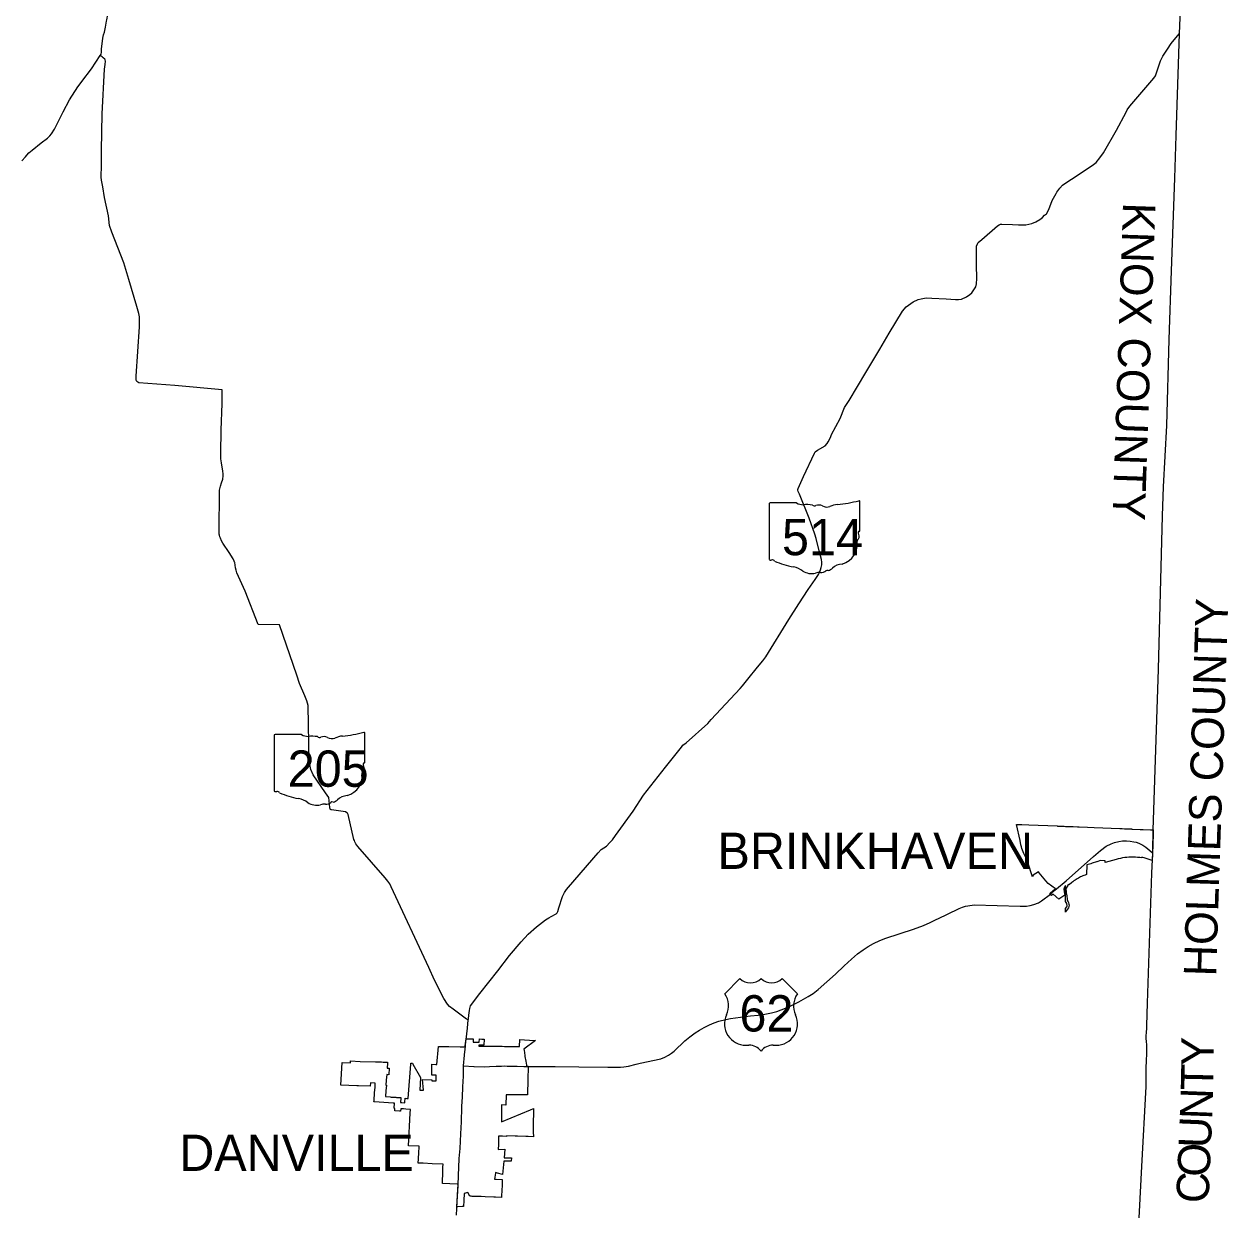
# Model space of a CAD drawing. Extents: x 1851937 to 2123937, y 789467 to 965467.
# Drawn here: x 2021685 to 2058846, y 888471 to 925060 of the extents above; entities that cross this region are included whole.
import ezdxf

# ---------------------------------------------------------------- set-up
doc = ezdxf.new("R2010")
doc.units = 0
for name, color, linetype in [('GM_X_Corporation', 7, 'Continuous'), ('GM_X_Corporation_Text', 7, 'Continuous'), ('GM_X_County', 7, 'Continuous'), ('GM_X_County_Text', 7, 'Continuous'), ('GM_X_State_Location', 7, 'Continuous'), ('GM_X_State_Route', 7, 'Continuous'), ('GM_X_State_Shield', 7, 'Continuous'), ('GM_X_US_Location', 7, 'Continuous'), ('GM_X_US_Route', 7, 'Continuous'), ('GM_X_US_Shield', 7, 'Continuous')]:
    doc.layers.add(name, color=color, linetype=linetype)

msp = doc.modelspace()

# ---------------------------------------------------------------- linework, layer by layer
at = {"layer": 'GM_X_Corporation'}
for points in [[(2052321, 900367), (2052352, 900365), (2052484, 900360), (2052703, 900351), (2053571, 900317), (2053588, 900316), (2053716, 900311), (2053718, 900311), (2053746, 900310), (2053776, 900308), (2053784, 900308), (2053794, 900308), (2053833, 900306), (2053913, 900303), (2053916, 900303), (2053922, 900303), (2053979, 900300), (2053982, 900300), (2053985, 900300), (2054057, 900297), (2054065, 900297), (2054208, 900291), (2054246, 900290), (2054254, 900289), (2054513, 900279), (2054719, 900271), (2055512, 900239), (2055579, 900236), (2055655, 900233), (2055792, 900228), (2055867, 900225), (2055883, 900224), (2055889, 900224), (2055898, 900224), (2056133, 900214), (2056231, 900210), (2056453, 900201), (2056542, 900198), (2056537, 900024), (2056536, 899999), (2056535, 899974), (2056531, 899854), (2056529, 899775), (2056527, 899731), (2056526, 899688), (2056521, 899532), (2056520, 899491), (2056518, 899449), (2056512, 899250), (2056449, 899275), (2056386, 899297), (2056322, 899318), (2056257, 899336), (2056192, 899352), (2056190, 899336), (2056124, 899344), (2056057, 899350), (2055991, 899354), (2055925, 899356), (2055858, 899355), (2055792, 899352), (2055725, 899347), (2055659, 899340), (2055593, 899330), (2055528, 899318), (2055463, 899304), (2055399, 899288), (2055056, 899194), (2055058, 899244), (2054915, 899249), (2054801, 899213), (2054787, 899208), (2054658, 899167), (2054613, 899153), (2054489, 899114), (2054480, 898818), (2054441, 898805), (2054403, 898791), (2054365, 898776), (2054328, 898759), (2054297, 898745), (2054267, 898729), (2054231, 898710), (2054195, 898689), (2054161, 898667), (2054127, 898644), (2054094, 898620), (2054061, 898595), (2054030, 898569), (2053948, 898500), (2053919, 898508), (2053907, 898478), (2053885, 898446), (2053856, 898402), (2053846, 898378), (2053843, 898356), (2053850, 898306), (2053858, 898247), (2053863, 898210), (2053870, 898159), (2053887, 898057), (2053887, 898049), (2053887, 898025), (2053891, 898012), (2053910, 897980), (2053920, 897957), (2053925, 897947), (2053936, 897910), (2053944, 897874), (2053940, 897830), (2053923, 897797), (2053836, 897665), (2053834, 897663), (2053834, 897665), (2053834, 897772), (2053871, 897827), (2053881, 897847), (2053883, 897871), (2053878, 897895), (2053869, 897923), (2053869, 897926), (2053857, 897952), (2053836, 897987), (2053834, 897993), (2053833, 898476), (2053803, 898430), (2053787, 898394), (2053785, 898375), (2053783, 898355), (2053790, 898298), (2053802, 898214), (2053807, 898174), (2053784, 898159), (2053630, 898057), (2053447, 898211), (2053404, 898175), (2053393, 898187), (2053354, 898232), (2053465, 898334), (2053519, 898381), (2053293, 898546), (2053228, 898622), (2053016, 898874), (2052995, 898899), (2052831, 898805), (2052815, 898748), (2052668, 899194), (2052651, 899230), (2052606, 899344), (2052547, 899468), (2052488, 899624), (2052470, 899674), (2052452, 899732), (2052431, 899865)], [(2032719, 893036), (2032769, 893034), (2032904, 893030), (2032902, 893000), (2032890, 892847), (2032956, 892844), (2032943, 892644), (2032878, 892647), (2032865, 892475), (2032855, 892325), (2032870, 892324), (2032857, 892145), (2032845, 891966), (2032987, 891957), (2033021, 891954), (2033163, 891945), (2033178, 891944), (2033318, 891935), (2033317, 891922), (2033308, 891786), (2033341, 891784), (2033441, 891778), (2033442, 891797), (2033447, 891917), (2033502, 891913), (2033542, 891911), (2033622, 892971), (2033624, 893001), (2033671, 892998), (2033688, 892967), (2033922, 892555), (2033902, 892168), (2034015, 892161), (2033987, 892497), (2034269, 892480), (2034268, 892459), (2034402, 892451), (2034408, 892586), (2034409, 892625), (2034275, 892630), (2034274, 892778), (2034273, 892936), (2034273, 892966), (2034397, 892959), (2034424, 892958), (2034480, 893517), (2034608, 893514), (2034801, 893509), (2035142, 893501), (2035273, 893498), (2035303, 893496), (2035305, 893514), (2035316, 893630), (2035318, 893655), (2035320, 893680), (2035327, 893754), (2035357, 893754), (2035466, 893752), (2035550, 893750), (2035546, 893649), (2035735, 893644), (2035739, 893746), (2035815, 893744), (2035886, 893743), (2035882, 893550), (2035808, 893551), (2035728, 893552), (2035726, 893528), (2035749, 893527), (2035807, 893527), (2035881, 893526), (2035986, 893525), (2036089, 893523), (2036228, 893522), (2036358, 893520), (2036362, 893520), (2036405, 893520), (2036446, 893519), (2036512, 893518), (2036578, 893518), (2036644, 893517), (2036710, 893516), (2036776, 893515), (2036792, 893515), (2036842, 893515), (2036849, 893514), (2036908, 893514), (2036974, 893513), (2036986, 893727), (2037426, 893698), (2037473, 893695), (2037114, 893431), (2037120, 893397), (2037144, 893235), (2037148, 893211), (2037148, 893207), (2037171, 893056), (2037190, 892934), (2037195, 892904), (2037246, 892904), (2037245, 892874), (2037236, 892509), (2037223, 892019), (2036593, 892025), (2036568, 892026), (2036555, 891698), (2036426, 891713), (2036418, 891193), (2037314, 891562), (2037408, 891601), (2037407, 891496), (2037406, 891434), (2037404, 891204), (2037402, 891068), (2037402, 890979), (2037401, 890944), (2037401, 890913), (2037403, 890884), (2037412, 890731), (2037245, 890736), (2037171, 890738), (2036917, 890746), (2036847, 890748), (2036581, 890760), (2036580, 890741), (2036573, 890741), (2036457, 890745), (2036396, 890747), (2036335, 890750), (2036331, 890645), (2036331, 890624), (2036330, 890603), (2036329, 890584), (2036329, 890569), (2036325, 890479), (2036325, 890463), (2036321, 890368), (2036320, 890338), (2036528, 890343), (2036504, 890073), (2036733, 890077), (2036724, 889977), (2036495, 889974), (2036458, 889565), (2036298, 889601), (2036242, 889625), (2036240, 889615), (2036239, 889607), (2036209, 889420), (2036254, 889418), (2036448, 889411), (2036442, 889276), (2036439, 889186), (2036436, 889126), (2036425, 888859), (2036239, 888865), (2036186, 888867), (2035915, 888876), (2035794, 888881), (2035713, 888883), (2035632, 888886), (2035521, 888890), (2035483, 888892), (2035448, 888893), (2035387, 889008), (2035269, 888982), (2035256, 888762), (2035245, 888577), (2035213, 888575), (2035076, 888569), (2035046, 888567), (2035056, 888752), (2035065, 888919), (2035066, 888938), (2035084, 889261), (2035058, 889262), (2035054, 889262), (2034599, 889287), (2034603, 889402), (2034608, 889557), (2034610, 889617), (2034612, 889692), (2034615, 889794), (2034618, 889883), (2034287, 889897), (2034004, 889909), (2033853, 889915), (2033854, 889932), (2033859, 890025), (2033860, 890044), (2033861, 890072), (2033865, 890143), (2033866, 890160), (2033867, 890176), (2033870, 890230), (2033880, 890413), (2033881, 890433), (2033560, 890447), (2033547, 890448), (2033602, 891460), (2033609, 891574), (2033470, 891583), (2033401, 891587), (2033391, 891588), (2033323, 891592), (2033312, 891593), (2033308, 891518), (2033272, 891520), (2033131, 891529), (2033134, 891604), (2033111, 891606), (2033113, 891642), (2033117, 891737), (2033119, 891767), (2033083, 891769), (2032499, 891806), (2032485, 891807), (2032487, 891837), (2032495, 891943), (2032498, 891987), (2032505, 892089), (2032511, 892166), (2032518, 892255), (2032524, 892344), (2032527, 892381), (2032376, 892389), (2032370, 892289), (2032007, 892301), (2031958, 892303), (2031464, 892319), (2031505, 893021), (2031760, 893013), (2031761, 893040), (2031763, 893070), (2032064, 893055), (2032532, 893041), (2032574, 893040), (2032640, 893038)]]:
    msp.add_lwpolyline(points, close=True, dxfattribs=at)
at = {"layer": 'GM_X_County'}
msp.add_lwpolyline([(2057387, 925735), (2057341, 924765), (2057236, 921624), (2057193, 920311), (2057098, 917443), (2057025, 915328), (2056946, 912676), (2056845, 910778), (2056821, 909883), (2056692, 905152), (2056529, 900191), (2056527, 900003), (2056520, 899740), (2056513, 899490), (2056492, 898858), (2056354, 894848), (2056334, 894166), (2056331, 894092), (2056325, 893939), (2056317, 893849), (2056312, 893777), (2056311, 893750), (2056318, 893677), (2056334, 893555), (2056336, 893469), (2056330, 893288), (2056319, 893081), (2056309, 892841), (2056314, 892278), (2056177, 889807), (2056002, 886440)], dxfattribs=at)
at = {"layer": 'GM_X_State_Route'}
for p, q in [((2029574, 906524), (2028910, 906536)), ((2035251, 892913), (2035278, 893241))]:
    msp.add_line(p, q, dxfattribs=at)
for points in [[(2024079, 924295), (2024091, 924454), (2024120, 924627), (2024142, 924729), (2024166, 924813), (2024178, 924861), (2024195, 924962), (2024225, 925154), (2024237, 925195), (2024266, 925358)], [(2053553, 919853), (2053564, 919874), (2053655, 919999), (2053741, 920091), (2053900, 920203), (2054126, 920351), (2054699, 920729), (2054777, 920789), (2054889, 920929), (2055003, 921089), (2055408, 921787), (2055703, 922344), (2055738, 922412), (2055816, 922525), (2056564, 923387), (2056606, 923460), (2056643, 923558), (2056731, 923835), (2056763, 923923), (2056834, 924072), (2056976, 924291), (2057097, 924461), (2057342, 924763)], [(2023418, 923218), (2023467, 923286), (2023766, 923681), (2023902, 923882), (2024034, 924087), (2024060, 924131), (2024071, 924196), (2024079, 924295)], [(2028910, 906536), (2028512, 907560), (2028248, 908130), (2028231, 908208), (2028214, 908286), (2028189, 908444), (2028185, 908462), (2028174, 908489), (2028140, 908564), (2028021, 908756), (2027822, 909043), (2027784, 909112), (2027745, 909197), (2027730, 909237), (2027716, 909287), (2027710, 909324), (2027706, 909359), (2027716, 910683), (2027747, 910800), (2027780, 910910), (2027816, 911014), (2027835, 911123), (2027829, 911187), (2027821, 911261), (2027783, 911525), (2027761, 911642), (2027758, 911816), (2027774, 912532), (2027798, 913358), (2027800, 913773), (2026334, 913904), (2025223, 913996), (2025197, 914012), (2025171, 914035), (2025159, 914050), (2025148, 914071), (2025144, 914093), (2025142, 914197), (2025247, 915720), (2025252, 915970), (2025249, 916031), (2025243, 916076), (2025232, 916134), (2025170, 916343), (2024920, 917178), (2024760, 917692), (2024397, 918645), (2024321, 918841), (2024296, 919139), (2024168, 919710), (2024114, 920041), (2024072, 920249), (2024065, 920338), (2024070, 920459), (2024072, 920586), (2024072, 921156), (2024093, 922294), (2024166, 923668), (2024188, 923818), (2024194, 923919), (2024189, 923955), (2024182, 923982), (2024130, 924023), (2024096, 924049), (2024034, 924087)], [(2021619, 920841), (2021725, 920964), (2021772, 921018), (2021836, 921085), (2021940, 921174), (2022214, 921395), (2022408, 921542), (2022484, 921610), (2022532, 921679), (2022622, 921819), (2022695, 921958), (2022897, 922355), (2023088, 922719), (2023347, 923120), (2023418, 923218)], [(2052386, 918870), (2052501, 918870), (2052612, 918867), (2052697, 918886), (2052790, 918910), (2052921, 918961), (2053042, 919035), (2053121, 919095), (2053188, 919163), (2053241, 919208), (2053314, 919342), (2053426, 919617), (2053542, 919833), (2053553, 919853)], [(2041489, 902130), (2041981, 902747), (2042022, 902806), (2042120, 902884), (2042796, 903479), (2042898, 903600), (2043788, 904564), (2043860, 904645), (2044025, 904847), (2044327, 905218), (2044494, 905414), (2044585, 905540), (2045297, 906690), (2045602, 907177), (2045886, 907615), (2046104, 907923), (2046209, 908079), (2046231, 908118), (2046271, 908222), (2046292, 908295), (2046310, 908377), (2046309, 908460), (2046299, 908535), (2046228, 908807), (2046140, 909185), (2046093, 909319), (2045920, 909811), (2045620, 910559), (2045584, 910637), (2045572, 910675), (2045569, 910693), (2045570, 910705), (2045577, 910728), (2045745, 911098), (2046085, 911820), (2046108, 911858), (2046174, 911909), (2046411, 912048), (2046472, 912120), (2046508, 912169), (2046576, 912304), (2046613, 912398), (2046877, 912891), (2047008, 913226), (2047153, 913443), (2047668, 914314), (2048101, 915027), (2048393, 915525), (2048805, 916203), (2048912, 916332), (2049129, 916493), (2049285, 916559), (2049380, 916587), (2049475, 916606), (2049552, 916610), (2049710, 916604), (2050146, 916587), (2050439, 916564), (2050533, 916561), (2050619, 916572), (2050780, 916644), (2050876, 916713), (2050937, 916765), (2050984, 916825), (2051026, 916890), (2051066, 916957), (2051088, 917043), (2051091, 917207), (2051083, 917637), (2051088, 918208), (2051111, 918283), (2051137, 918320), (2051248, 918418), (2051735, 918836), (2051785, 918870), (2051828, 918886), (2051868, 918886), (2052192, 918877), (2052386, 918870)], [(2031606, 900750), (2031170, 900815), (2031161, 900818), (2031153, 900823), (2031145, 900828), (2031138, 900837), (2031133, 900848), (2031128, 900865), (2031124, 900888), (2031091, 901195), (2030993, 901343), (2030607, 901899), (2030538, 902063), (2030515, 902159), (2030502, 902199), (2030486, 902283), (2030456, 904037), (2030412, 904181), (2030352, 904330), (2030186, 904712), (2030102, 904976), (2029574, 906524)], [(2035394, 894333), (2035401, 894372), (2035413, 894479), (2035431, 894627), (2035441, 894690), (2035464, 894765), (2035751, 895146), (2036305, 895851), (2036674, 896320), (2037033, 896738), (2037249, 896975), (2037503, 897207), (2037780, 897420), (2037883, 897481), (2037959, 897529), (2038107, 897604), (2038122, 897616), (2038137, 897633), (2038158, 897674), (2038194, 897796), (2038304, 898144), (2038365, 898262), (2038425, 898353), (2038490, 898429), (2039407, 899484), (2039498, 899587), (2039661, 899696), (2039771, 899804), (2039848, 899893), (2039939, 900024), (2040486, 900777), (2040801, 901265), (2041489, 902130)], [(2031882, 899866), (2031869, 899901), (2031691, 900670), (2031679, 900697), (2031668, 900711), (2031648, 900727), (2031606, 900750)], [(2035394, 894333), (2035342, 894353), (2034930, 894661), (2034814, 894748), (2034754, 894817), (2034645, 894996), (2034351, 895561), (2034180, 895951), (2033012, 898444), (2032972, 898530), (2032913, 898612), (2032828, 898722), (2031990, 899686), (2031926, 899764), (2031895, 899827), (2031882, 899866)], [(2035330, 893731), (2035369, 894074), (2035394, 894333)], [(2035311, 893515), (2035313, 893532), (2035324, 893682), (2035330, 893731)], [(2035278, 893241), (2035279, 893258), (2035301, 893431), (2035311, 893515)]]:
    msp.add_lwpolyline(points, dxfattribs=at)
at = {"layer": 'GM_X_State_Shield'}
for p, q in [((2044685, 910254), (2044685, 908553)), ((2045533, 910284), (2044712, 910284)), ((2047486, 909436), (2047486, 910326)), ((2047486, 909436), (2047486, 909436)), ((2029404, 903108), (2029404, 901407)), ((2030252, 903138), (2029432, 903138)), ((2032206, 902290), (2032206, 903180)), ((2032206, 902290), (2032206, 902290))]:
    msp.add_line(p, q, dxfattribs=at)
for centre, major_axis, start_param, end_param in [((2044717, 910258), (32.5, 0), 1.712693, 3.28349), ((2045728, 910481), (315, 0), 4.042523, 4.731795), ((2045832, 909329), (1130, 0), 1.404758, 1.657858), ((2046089, 910267), (90.8, 0), 3.836095, 5.185415), ((2046222, 910070), (189, 0), 0.950623, 2.079405), ((2046466, 910340), (227, 0), 4.081561, 5.145723), ((2046867, 909764), (598, 0), 1.699011, 2.107814), ((2046488, 912603), (2971, 0), 4.814394, 5.042369), ((2047455, 910330), (31.2, 0), 6.141152, 7.989035), ((2047479, 909371), (48.3, 0), 1.883978, 3.671073), ((2047172, 909258), (290, 0), 5.934695, 6.695948), ((2047453, 909433), (33.4, 0), 5.05454, 6.418171), ((2046655, 908950), (743, 0), 5.101752, 6.440018), ((2047598, 909064), (211, 0), 2.387724, 3.262537), ((2044717, 908550), (32.7, 0), 3.00124, 4.508301), ((2044722, 908724), (250, 0), 4.665946, 4.897461), ((2044773, 908455), (90.1, 0), 0.519207, 1.627899), ((2045911, 909984), (2146, 0), 4.195997, 4.488961), ((2045271, 907789), (671, 0), 0.823519, 1.323587), ((2046452, 908388), (240, 0), 4.937069, 5.64225), ((2046968, 908076), (407, 0), 1.647645, 2.488434), ((2045997, 908447), (426, 0), 4.026481, 4.996735), ((2046243, 907859), (350, 0), 1.495662, 1.94098), ((2046274, 908319), (227, 0), 4.691044, 5.507374), ((2046480, 908155), (63.9, 0), 1.147584, 2.315152), ((2029436, 903112), (32.5, 0), 1.712693, 3.28349), ((2030448, 903335), (315, 0), 4.042523, 4.731795), ((2030552, 902183), (1130, 0), 1.404758, 1.657858), ((2030809, 903121), (90.8, 0), 3.836095, 5.185415), ((2030942, 902924), (189, 0), 0.950623, 2.079405), ((2031186, 903194), (227, 0), 4.081561, 5.145723), ((2031587, 902618), (598, 0), 1.699011, 2.107814), ((2031208, 905457), (2971, 0), 4.814394, 5.042369), ((2032175, 903183), (31.2, 0), 6.141152, 7.989035), ((2032173, 902286), (33.4, 0), 5.05454, 6.418171), ((2031374, 901804), (743, 0), 5.101752, 6.440018), ((2032318, 901917), (211, 0), 2.387724, 3.262537), ((2032199, 902224), (48.3, 0), 1.883978, 3.671073), ((2031892, 902112), (290, 0), 5.934695, 6.695948), ((2029437, 901403), (32.7, 0), 3.00124, 4.508301), ((2029441, 901577), (250, 0), 4.665946, 4.897461), ((2029493, 901309), (90.1, 0), 0.519207, 1.627899), ((2030630, 902837), (2146, 0), 4.195997, 4.488961), ((2029991, 900643), (671, 0), 0.823519, 1.323587), ((2031688, 900930), (407, 0), 1.647645, 2.488434), ((2030717, 901301), (426, 0), 4.026481, 4.996735), ((2030963, 900712), (350, 0), 1.495662, 1.94098), ((2030994, 901173), (227, 0), 4.691044, 5.507374), ((2031199, 901008), (63.9, 0), 1.147584, 2.315152), ((2031172, 901242), (240, 0), 4.937069, 5.64225)]:
    msp.add_ellipse(centre, major_axis=major_axis, ratio=0.8, start_param=start_param, end_param=end_param, dxfattribs=at)
at = {"layer": 'GM_X_US_Route'}
for p, q in [((2035245, 892598), (2035251, 892913)), ((2035251, 892913), (2035569, 892897)), ((2037108, 892901), (2037213, 892900)), ((2035063, 888891), (2035080, 889209))]:
    msp.add_line(p, q, dxfattribs=at)
for points in [[(2053508, 898334), (2053556, 898376), (2053848, 898629), (2054698, 899375), (2054912, 899561), (2055092, 899694), (2055238, 899770), (2055350, 899805), (2055476, 899840), (2055588, 899858), (2055720, 899857), (2055831, 899851), (2055941, 899832), (2056011, 899813), (2056094, 899784), (2056216, 899728), (2056313, 899665), (2056375, 899617), (2056440, 899563), (2056514, 899487)], [(2050382, 897692), (2050550, 897770), (2050649, 897810), (2050750, 897842), (2050817, 897858), (2051017, 897886), (2052435, 897839), (2052625, 897846), (2052739, 897860), (2052858, 897896), (2052994, 897946), (2053096, 898005), (2053371, 898216), (2053508, 898334)], [(2040021, 892874), (2040093, 892877), (2040204, 892886), (2040340, 892911), (2040581, 892967), (2040700, 892998), (2041345, 893134), (2041461, 893185), (2041580, 893249), (2041672, 893310), (2041753, 893374), (2041846, 893459), (2041989, 893600), (2042083, 893691), (2042238, 893810), (2042397, 893939), (2042531, 894022), (2042679, 894102), (2042839, 894180), (2042989, 894239), (2043135, 894291), (2043347, 894350), (2043493, 894378), (2044104, 894461), (2044346, 894480), (2044500, 894503), (2044761, 894555), (2044924, 894598), (2045190, 894701), (2045356, 894772), (2045596, 894887), (2045675, 894929), (2045747, 894969), (2045884, 895051), (2046040, 895152), (2046202, 895268), (2046729, 895741), (2046996, 895998), (2047222, 896207), (2047409, 896368), (2047585, 896496), (2047738, 896600), (2047907, 896693), (2048104, 896781), (2048291, 896855), (2049136, 897130), (2049444, 897249), (2049655, 897336), (2049779, 897396), (2050152, 897577), (2050354, 897679), (2050382, 897692)], [(2035569, 892897), (2035574, 892897), (2035888, 892887), (2036057, 892896), (2036256, 892906), (2036399, 892911), (2036420, 892911)], [(2036420, 892911), (2036509, 892912), (2036594, 892908), (2036897, 892903)], [(2036897, 892903), (2036908, 892902), (2037108, 892901)], [(2037213, 892900), (2037413, 892898), (2038078, 892894), (2038809, 892885), (2039708, 892875), (2039944, 892871), (2040021, 892874)], [(2035198, 891642), (2035199, 891668), (2035215, 891948), (2035234, 892265), (2035245, 892593), (2035245, 892598)], [(2035121, 890053), (2035142, 890365), (2035164, 890816), (2035185, 891185), (2035198, 891642)], [(2035080, 889209), (2035081, 889231), (2035098, 889530), (2035120, 890043), (2035121, 890053)], [(2035035, 888308), (2035054, 888721), (2035063, 888891)]]:
    msp.add_lwpolyline(points, dxfattribs=at)
at = {"layer": 'GM_X_US_Shield'}
for p, q in [((2043781, 895610), (2043314, 895143)), ((2045556, 895143), (2045089, 895610)), ((2043968, 893555), (2044062, 893555)), ((2044809, 893555), (2044902, 893555))]:
    msp.add_line(p, q, dxfattribs=at)
for centre, radius, start, end in [((2044108, 895944), 467, 225.573, 314.427), ((2044762, 895944), 467, 225.573, 314.427), ((2042779, 894768), 654, 334.5471, 35.0009), ((2046091, 894768), 654, 144.9991, 205.4529), ((2043961, 894209), 654, 154.8319, 270.6383), ((2044909, 894209), 654, 269.3617, 25.1681), ((2044062, 893089), 467, 36.8699, 90), ((2044809, 893089), 467, 90, 143.1301)]:
    msp.add_arc(centre, radius, start, end, dxfattribs=at)

# ---------------------------------------------------------------- texts
at = {"layer": 'GM_X_Corporation_Text'}
for s, p in [('BRINKHAVEN', (2043090, 898992)), ('DANVILLE', (2026475, 889674))]:
    msp.add_text(s, height=1120, rotation=0, dxfattribs=at).set_placement(p)
at = {"layer": 'GM_X_County_Text'}
for s, rotation, p in [('KNOX COUNTY', 268.087, (2055609, 919565)), ('HOLMES COUNTY', 88.1414, (2058480, 895666)), ('Y', 89.5735, (2058405, 892914)), ('T', 88.8049, (2058389, 892152)), ('N', 87.8797, (2058356, 891250)), ('U', 87.6383, (2058319, 890362)), ('O', 87.5558, (2058281, 889477)), ('C', 87.5395, (2058246, 888663))]:
    msp.add_text(s, height=1000, rotation=rotation, dxfattribs=at).set_placement(p)
at = {"layer": 'GM_X_State_Location'}
for s, p in [('514', (2050735, 917779)), ('205', (2030433, 901838))]:
    msp.add_text(s, height=1, rotation=0, dxfattribs=at).set_placement(p)
for s, p in [('s', (2051088, 917852)), ('r', (2051088, 917852)), ('s', (2030786, 901911)), ('r', (2030786, 901911))]:
    msp.add_text(s, height=1, dxfattribs=at).set_placement(p)
at = {"layer": 'GM_X_State_Shield'}
for s, p in [('514', (2045080, 908673)), ('205', (2029822, 901527))]:
    msp.add_text(s, height=1120.7, dxfattribs=at).set_placement(p)
at = {"layer": 'GM_X_US_Location'}
for s in ['0', '/']:
    msp.add_text(s, height=1, dxfattribs=at).set_placement((2044839, 894512))
msp.add_text('62', height=1, rotation=0, dxfattribs=at).set_placement((2044632, 894305))
at = {"layer": 'GM_X_US_Shield'}
msp.add_text('62', height=1120.7, dxfattribs=at).set_placement((2043766, 893976))

doc.saveas('drawing.dxf')
